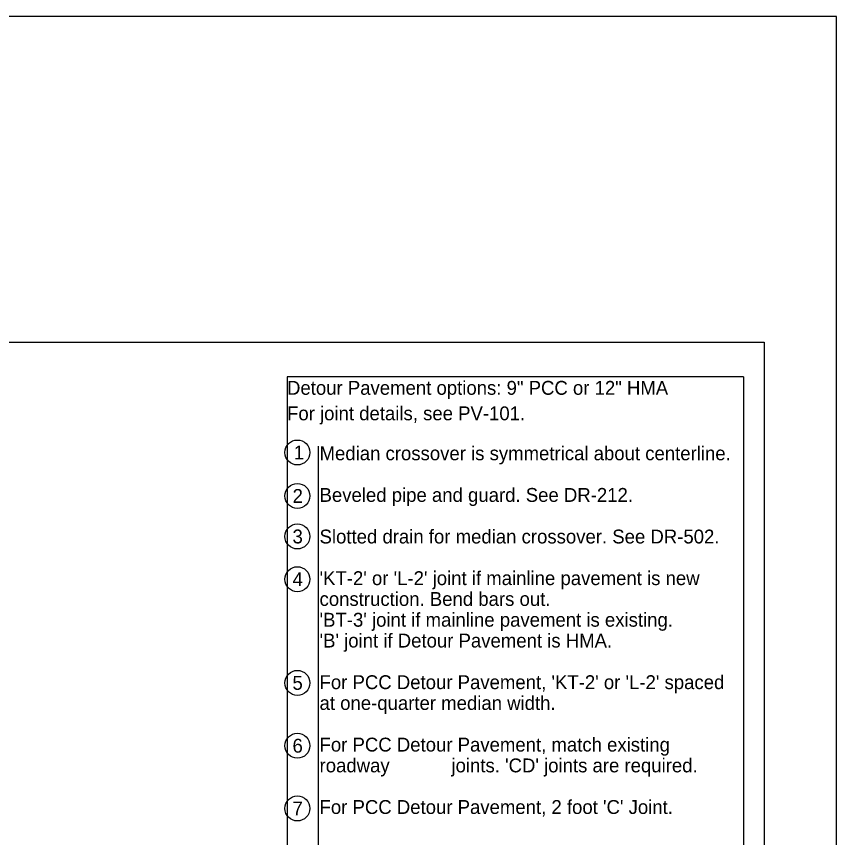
# Model space of a CAD drawing. Extents: x -2135039 to -2131695, y -2139150 to -2136566.
# Drawn here: x -2132878 to -2131695, y -2137750 to -2136566 of the extents above; entities that cross this region are included whole.
import ezdxf

# ---------------------------------------------------------------- set-up
doc = ezdxf.new("R2010")
doc.units = 0
for name, color, linetype in [('dsnDOTLogo', 7, 'Continuous'), ('dsnNonPlotable', 7, 'Continuous'), ('Level 1', 7, 'Continuous'), ('Level 2', 7, 'Continuous')]:
    doc.layers.add(name, color=color, linetype=linetype)

msp = doc.modelspace()

# ---------------------------------------------------------------- linework, layer by layer
at = {"layer": 'dsnDOTLogo'}
msp.add_lwpolyline([(-2135038.9, -2139150.4), (-2131694.9, -2139150.4), (-2131694.9, -2136566.4), (-2135038.9, -2136566.4)], close=True, dxfattribs=at)
at = {"layer": 'dsnNonPlotable'}
for p, q in [((-2132487.5, -2137085.9), (-2132487.5, -2138555.9)), ((-2131829.4, -2137085.9), (-2132487.5, -2137085.9)), ((-2131829.4, -2137085.9), (-2131829.4, -2138555.9)), ((-2132442.5, -2137185.9), (-2132442.5, -2138177.5))]:
    msp.add_line(p, q, dxfattribs=at)
at = {"layer": 'Level 1'}
msp.add_lwpolyline([(-2134934.4, -2137035.9), (-2131799.4, -2137035.9), (-2131799.4, -2139045.9), (-2134934.4, -2139045.9)], close=True, dxfattribs=at)
at = {"layer": 'Level 2'}
for centre in [(-2132472.5, -2137195.2), (-2132472.5, -2137257.9), (-2132472.5, -2137316.3), (-2132472.5, -2137377.9), (-2132472.5, -2137527.4), (-2132472.5, -2137618), (-2132472.5, -2137708.5)]:
    msp.add_circle(centre, 18, dxfattribs=at)

# ---------------------------------------------------------------- texts
at = {"layer": 'Level 1'}
for s, p in [('Detour Pavement options: 9" PCC or 12" HMA  ', (-2132487.5, -2137112)), ('For joint details, see PV-101.', (-2132487.5, -2137148.8)), ('1', (-2132477.7, -2137205.2)), ('Median crossover is symmetrical about centerline.', (-2132440.6, -2137206.4)), ('Beveled pipe and guard. See DR-212.', (-2132440.6, -2137266.4)), ('2', (-2132479.5, -2137267.9)), ('3', (-2132479.6, -2137326.3)), ('Slotted drain for median crossover. See DR-502.', (-2132440.6, -2137326.4)), ('4', (-2132479.5, -2137387.9)), ("'KT-2' or 'L-2' joint if mainline pavement is new  ", (-2132440.6, -2137386.4)), ('construction. Bend bars out.', (-2132440.6, -2137416.4)), ("'BT-3' joint if mainline pavement is existing. ", (-2132440.6, -2137446.4)), ("'B' joint if Detour Pavement is HMA. ", (-2132440.6, -2137476.4)), ('5', (-2132479.7, -2137537.4)), ("For PCC Detour Pavement, 'KT-2' or 'L-2' spaced ", (-2132440.6, -2137536.4)), ('at one-quarter median width.', (-2132440.6, -2137566.4)), ('6', (-2132479.6, -2137628)), ('For PCC Detour Pavement, match existing ', (-2132440.6, -2137626.4)), ("roadway            joints. 'CD' joints are required. ", (-2132440.6, -2137656.4)), ("For PCC Detour Pavement, 2 foot 'C' Joint.", (-2132440.6, -2137716.4)), ('7', (-2132479.6, -2137718.5))]:
    msp.add_text(s, height=20, dxfattribs=at).set_placement(p)

doc.saveas('drawing.dxf')
